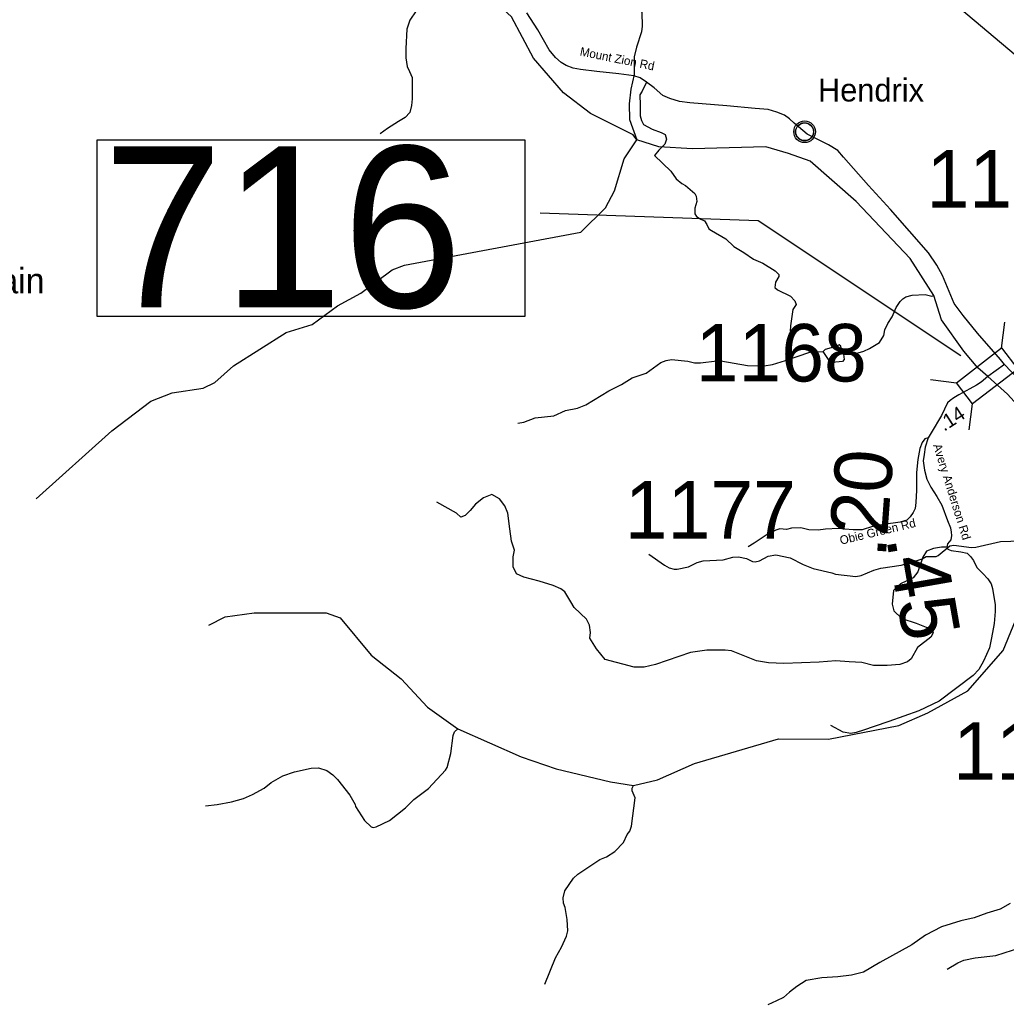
# Model space of a CAD drawing. Extents: x 1248089 to 1457196, y 820910 to 988753.
# Drawn here: x 1280420 to 1288997, y 872206 to 880738 of the extents above; entities that cross this region are included whole.
import ezdxf

# ---------------------------------------------------------------- set-up
doc = ezdxf.new("R2010")
doc.units = 0
for name, color, linetype in [('Exist Civil Demographics Community CELL', 7, 'Continuous'), ('Exist Civil Demographics Community Label', 7, 'Continuous'), ('Exist Geographical Mountain Summit Label', 7, 'Continuous'), ('Exist Hydrographic Creek Single Shore', 7, 'Continuous'), ('Exist Hydrographic Misc Water Feature', 7, 'Continuous'), ('Exist Road Non-System Type 51', 7, 'Continuous'), ('Exist Road Secondary Structure Standard Bridge CELL', 7, 'Continuous'), ('Exist Road Secondary Structure Standard Bridge Number Label', 7, 'Continuous'), ('Exist Road Secondary Type 41 Attributed', 7, 'Continuous'), ('Exist Road Secondary Type 51 Attributed', 7, 'Continuous'), ('Exist Road Secondary Type 51 Label', 7, 'Continuous'), ('Prop GRAU CAT1 Cell', 7, 'Continuous'), ('Prop Lane Lines', 7, 'Continuous')]:
    doc.layers.add(name, color=color, linetype=linetype)

msp = doc.modelspace()

# ---------------------------------------------------------------- linework, layer by layer
at = {"layer": 'Exist Civil Demographics Community CELL'}
msp.add_lwpolyline([(1287166.1, 879776.9), (1287167.1, 879782.5), (1287168.8, 879789.1), (1287171.8, 879796.3), (1287174.7, 879802), (1287178, 879807.7), (1287181.8, 879812.9), (1287185.7, 879817.2), (1287190.3, 879821.8), (1287195.9, 879826.4), (1287201.3, 879830.1), (1287206.2, 879832.9), (1287211.2, 879835.4), (1287216.7, 879837.7), (1287222.3, 879839.5), (1287226.6, 879840.7), (1287231.5, 879841.4), (1287235.6, 879842.1), (1287242, 879842.4), (1287246.4, 879842.3), (1287252.1, 879842), (1287257, 879841.3), (1287261.9, 879840.3), (1287266.9, 879838.9), (1287272.1, 879837), (1287278.7, 879834), (1287285, 879830.5), (1287290, 879827), (1287295.2, 879823), (1287298.5, 879819.8), (1287302.6, 879815.5), (1287306.5, 879810.8), (1287309.6, 879806.2), (1287312.7, 879801.2), (1287315.2, 879796), (1287317.2, 879791), (1287318.8, 879786), (1287320, 879781.4), (1287321.1, 879775.3), (1287321.8, 879770.6), (1287322, 879764.6), (1287321.8, 879758.8), (1287321.3, 879753.2), (1287320.3, 879747.7), (1287318.7, 879741.5), (1287316.8, 879735.7), (1287314.5, 879730.6), (1287311.4, 879724.6), (1287308.1, 879719.3), (1287304.6, 879714.6), (1287300.4, 879709.9), (1287295.1, 879704.9), (1287290.1, 879700.8), (1287285.1, 879697.3), (1287280.8, 879694.8), (1287273.9, 879691.6), (1287266.8, 879688.9), (1287260.9, 879687.4), (1287254.2, 879686.1), (1287249.8, 879685.6), (1287245.3, 879685.4), (1287239.7, 879685.4), (1287235.5, 879685.8), (1287229.8, 879686.5), (1287223.9, 879687.8), (1287219.3, 879689.1), (1287214.2, 879691), (1287209.6, 879693), (1287205.6, 879695.2), (1287198.8, 879699.3), (1287193.3, 879703.6), (1287188.3, 879708.1), (1287183.9, 879712.9), (1287180.7, 879716.9), (1287177.7, 879721.1), (1287173.6, 879728.2), (1287171.9, 879731.7), (1287170.2, 879735.7), (1287167.6, 879743.9), (1287166.1, 879751), (1287165.4, 879756.1), (1287165.1, 879762.4), (1287165, 879767.1), (1287165.5, 879773.6)], close=True, dxfattribs=at)
for centre, radius in [((1287243.7, 879764.5), 94.3), ((1287243.4, 879764.8), 76.7)]:
    msp.add_circle(centre, radius, dxfattribs=at)
at = {"layer": 'Exist Hydrographic Creek Single Shore'}
for points in [[(1285785.8, 879695.4), (1285753.7, 879738.6), (1285382.7, 879923.3), (1285145.7, 880102.1), (1284885.7, 880402.7), (1284694.7, 880764.4), (1284596.7, 880851.8), (1284298.6, 880923.3), (1283947.7, 880907.4), (1283419.7, 881147.8)], [(1288835.1, 877637.2), (1288749.2, 877712.6), (1288628.5, 877856), (1288432.8, 878128.9), (1288366.5, 878339.5), (1288161.8, 878662.8), (1287690.8, 879158.1), (1287290.7, 879507.6), (1287102.6, 879575.8), (1286906.6, 879634.6), (1286267.7, 879616.7), (1285975.7, 879632.4), (1285785.8, 879695.4)], [(1289907.9, 876073.7), (1289876.8, 876159.8), (1289306.8, 876706.3), (1289236.9, 876917.8), (1289312.5, 877116.4), (1289121.9, 877354.4), (1289008.6, 877483.6), (1288835.1, 877637.2)]]:
    msp.add_lwpolyline(points, dxfattribs=at)
at = {"layer": 'Exist Hydrographic Misc Water Feature'}
for points in [[(1285848.1, 881734.3), (1285875.3, 881700.9), (1285909.6, 881636.2), (1285915.8, 881556.5), (1285881.7, 881393), (1285875.8, 881312.7), (1285822.5, 881184.2), (1285813.4, 881140.8), (1285813.2, 880884), (1285819.6, 880819.8), (1285827.1, 880799.9), (1285830.4, 880683.3), (1285825, 880631.7), (1285781.7, 880498.9), (1285761.7, 880415.5), (1285761.9, 880262.9), (1285732.7, 880133.8), (1285717.6, 880006), (1285720.2, 879869.8), (1285785.8, 879695.4)], [(1280563.7, 876573.1), (1281220.7, 877163.9), (1281560.7, 877423), (1281745.7, 877494.8), (1282013.7, 877535.4), (1282114.7, 877585.8), (1282276.7, 877730.4), (1282734.7, 878019.9), (1282960.6, 878087.6), (1283181.7, 878250.6), (1283384.7, 878361.4), (1283656.7, 878562.8), (1283765.7, 878603.3), (1285298.8, 878891), (1285512.7, 879103.3), (1285591.7, 879249.5), (1285673.7, 879530.1), (1285785.8, 879695.4)], [(1287581.6, 877830.7), (1287669.6, 877830.6), (1287758.3, 877856.8), (1287808.9, 877879.5), (1287894.2, 877931.2), (1287931.8, 877994.5), (1287941, 878041.8), (1287966.4, 878097.2), (1288003.8, 878156.4), (1288039.9, 878237.7), (1288073.1, 878288.7), (1288097.7, 878312), (1288122.1, 878328), (1288178.5, 878342.4), (1288290.8, 878350), (1288350.4, 878336.5), (1288366.5, 878339.5)], [(1287581.6, 877830.7), (1287569.9, 877847.4), (1287559.1, 877899.3), (1287543.5, 877911.9), (1287515.1, 877896.1), (1287422.5, 877870.9), (1287406, 877854.8)], [(1284748.8, 877231.8), (1284801.1, 877240.6), (1284902.1, 877278), (1285062.7, 877296.2), (1285163.8, 877341.7), (1285268.3, 877361), (1285341.2, 877391.5), (1285542.4, 877512.2), (1285651.8, 877565.8), (1285745.3, 877625.5), (1285866.3, 877666.6), (1285994.6, 877757.5), (1286039.1, 877776.3), (1286087.4, 877783.6), (1286227.1, 877770.1), (1286286.8, 877756.6), (1286338.8, 877755.6), (1286479.3, 877774), (1286515.3, 877772.5), (1286746.5, 877733.4), (1286890.6, 877729.7), (1286963, 877742.3), (1287075.8, 877775.3), (1287289.7, 877848.1), (1287406, 877854.8)], [(1287581.6, 877830.7), (1287588.5, 877784.7), (1287573.9, 877766.9), (1287483.7, 877757.2), (1287463.8, 877765.8), (1287406, 877854.8)], [(1285887.7, 876092.8), (1286025.6, 875997.4), (1286064.9, 875974.4), (1286108.6, 875961.2), (1286136.7, 875960.7), (1286233.3, 875982.5), (1286310.2, 876018.7), (1286362.7, 876033.3), (1286534.9, 876043), (1286619.5, 876065), (1286667.7, 876068.2), (1286739.3, 876054.5), (1286790.8, 876028.7), (1286814.7, 876026.7), (1286850.9, 876033.4), (1286926, 876075.3), (1286994.3, 876086.3), (1287117.8, 876060.8), (1287230.3, 876001.9), (1287317.6, 875968.1), (1287480.8, 875929.6), (1287512.6, 875917.5), (1287688.2, 875898.3), (1287736.4, 875905.6), (1287845.6, 875952.7), (1287906.1, 875971.1), (1288082.8, 875997.2), (1288165.5, 876019.3), (1288266.4, 876052.5), (1288298.9, 876071.6), (1288386.9, 876071.5), (1288403.1, 876079.4), (1288505.4, 876165.1), (1288541.4, 876170.1), (1288693.1, 876150.6), (1288733.2, 876153.2), (1288946.5, 876202.2), (1289126.9, 876207.6)], [(1282062.7, 875476), (1282206.8, 875548.6), (1282457.8, 875583.1), (1283082.8, 875583.6), (1283206.7, 875538.5), (1283473.8, 875214.7), (1283735.7, 875009.1), (1283963.8, 874761.7), (1284227.4, 874575), (1284778.8, 874331.7), (1285084.8, 874227), (1285556.8, 874112.6), (1285756.3, 874080.6), (1285965.8, 874130.7), (1286286.8, 874272), (1287016.9, 874487.2), (1287450.9, 874485), (1288062.9, 874604), (1288314.9, 874713.8), (1288661.9, 874903.9), (1288970.8, 875255.5), (1289209.8, 875841.6)], [(1282035.5, 873905.8), (1282135.7, 873915.3), (1282260.4, 873938.2), (1282365.2, 873968.1), (1282442.1, 874001.9), (1282543.6, 874058.1), (1282606.8, 874108.5), (1282708.2, 874164), (1282809.2, 874201.3), (1282954.1, 874232.1), (1283018.2, 874234), (1283089.6, 874212.1), (1283140.8, 874175), (1283183.7, 874132.2), (1283290.5, 873997.2), (1283336.5, 873915.8), (1283340.1, 873900.2), (1283417.2, 873778), (1283473.9, 873721), (1283493.7, 873716.5), (1283518, 873723.4), (1283633.4, 873778.5), (1283772.1, 873887.4), (1283846, 873959.8), (1283974.4, 874054.8), (1284122.4, 874215.2), (1284135, 874238.7), (1284168.1, 874360.3), (1284187.9, 874515.9), (1284200.7, 874547.6), (1284227.4, 874575)], [(1285159.3, 873165.3), (1285234.3, 873277), (1285271, 873310), (1285464.3, 873437.4), (1285521, 873462.5), (1285594.1, 873508.6), (1285668.1, 873585.1), (1285701.8, 873655.9), (1285724.5, 873683.3), (1285737.7, 873727.3), (1285769.7, 873974.5), (1285743.2, 874035), (1285743.7, 874057.2), (1285756.3, 874080.6)], [(1284985.1, 872353.8), (1285076.8, 872583.5), (1285131.1, 872675.8), (1285173.6, 872771.1), (1285184.6, 872819.3), (1285179, 872915.3), (1285161.6, 873019.9), (1285146.6, 873059.7), (1285145.6, 873103.8), (1285159.3, 873165.3)], [(1288482.7, 872483.9), (1288576.2, 872541.1), (1288628.8, 872563.9), (1288725.3, 872584.1), (1288905.9, 872603.4), (1289123.8, 872672.1), (1289223.9, 872673.4), (1289295.5, 872658), (1289383.5, 872652.1), (1289495.8, 872661.4), (1289632.6, 872695.6), (1289657.1, 872711.5), (1289697.2, 872718.1), (1289810.6, 872771.6), (1289869.5, 872804.1), (1289898.8, 872855.3), (1289938.7, 873004.1), (1289955.4, 873023.3), (1289985.9, 873048.8)]]:
    msp.add_lwpolyline(points, dxfattribs=at)
at = {"layer": 'Exist Road Non-System Type 51'}
for points in [[(1284008.2, 881092.6), (1283967.8, 881032), (1283933, 880948), (1283900.2, 880866), (1283865.4, 880814.8), (1283812.2, 880734.8), (1283785.6, 880654.9), (1283775.3, 880488.9), (1283775.3, 880406.9), (1283787.6, 880330.3), (1283808.1, 880287.2), (1283830.6, 880236), (1283830.6, 880141.7), (1283830.6, 880049.5), (1283826.5, 879992.1), (1283810.1, 879932.7), (1283771.2, 879889.6), (1283713.9, 879854.8), (1283615.6, 879793.3), (1283552.4, 879747)], [(1285868.8, 880195), (1285830.6, 880116.1), (1285811.6, 880086.2), (1285814.3, 879996.8), (1285814.3, 879901.9), (1285825.1, 879861.2), (1285844.1, 879825.9), (1285917.3, 879788), (1285995.8, 879758.2), (1286031.1, 879739.2), (1286041.9, 879698.5), (1286028.3, 879657.8), (1285976.9, 879603.6), (1285938.9, 879557.5), (1286079.7, 879420.5), (1286125.8, 879355.5), (1286174.5, 879314.8), (1286207, 879298.5), (1286247.7, 879263.3), (1286288.3, 879228), (1286299.2, 879203.6), (1286307.3, 879157.5), (1286288.3, 879100.6), (1286288.3, 879051.8), (1286304.6, 879027.4), (1286342.5, 879003), (1286372.3, 878989.4), (1286394, 878956.9), (1286410.3, 878921.6), (1286434.6, 878905.4), (1286559.3, 878832.2), (1286627, 878767.1), (1286713.7, 878715.6), (1286797.7, 878655.9), (1286879, 878620.7), (1286987.4, 878555.6), (1287019, 878524.3), (1287019, 878505.3), (1286989.2, 878456.5), (1286983.8, 878410.4), (1287008.2, 878388.7), (1287122, 878334.5), (1287157.2, 878293.8), (1287170.8, 878264), (1287141, 878217.9), (1287138.3, 878198.9), (1287119.3, 878076.9), (1287116.6, 878030.8)], [(1288481.1, 876154), (1288434.4, 876153.3), (1288365.3, 876142.4), (1288303.6, 876117), (1288270.9, 876066.1), (1288227.3, 875938.9), (1288187.4, 875888), (1288078.4, 875833.5), (1288016.6, 875775.3), (1288005.7, 875659), (1288020.3, 875600.8), (1288089.3, 875531.7), (1288212.8, 875491.8), (1288300, 875459), (1288350.8, 875440.9), (1288361.7, 875408.2), (1288339.9, 875371.8), (1288223.7, 875280.9), (1288169.2, 875182.8), (1288136.5, 875157.3), (1288071.1, 875131.9), (1287962.2, 875124.6), (1287842.3, 875124.6), (1287740.6, 875150.1), (1287631.6, 875157.3), (1287515.4, 875164.6), (1287370.1, 875153.7), (1287061.3, 875142.8), (1286930.6, 875146.4), (1286825.2, 875164.6), (1286607.3, 875251.9), (1286552.8, 875259.1), (1286393, 875259.1), (1286251.3, 875237.3), (1285946.2, 875131.9), (1285849.5, 875110.2), (1285762.4, 875110.2), (1285508.1, 875175.6), (1285435.4, 875270.1), (1285377.3, 875361), (1285381, 875411.9), (1285373.7, 875473.7), (1285348.3, 875528.2), (1285239.3, 875630), (1285210.2, 875677.3), (1285159.4, 875764.5), (1285123.1, 875789.9), (1285057.7, 875819), (1284934.2, 875859), (1284803.4, 875891.7), (1284738, 875920.8), (1284709, 875982.6), (1284709, 876069.8), (1284719.9, 876128), (1284694.4, 876204.3), (1284680.7, 876311.9), (1284662.5, 876450.1), (1284637.1, 876511.9), (1284589.9, 876573.7), (1284524.5, 876610), (1284451.8, 876580.9), (1284382.8, 876526.4), (1284335.6, 876471.9), (1284292, 876428.3), (1284255.7, 876413.7), (1284215.7, 876450.1), (1284045, 876544.6)], [(1287834.7, 876331.7), (1287743.6, 876304.2), (1287666.9, 876304.2), (1287593.1, 876310.1), (1287537, 876316), (1287424.8, 876310.1), (1287359.8, 876301.2), (1287280.1, 876304.2), (1287209.3, 876321.9), (1287129.5, 876319), (1287085.3, 876307.1), (1287029.2, 876313.1), (1286952.4, 876286.5), (1286804.8, 876189), (1286751.6, 876156.5)], [(1288708.9, 875037.8), (1288412.8, 874814.3), (1288235.7, 874731.5), (1287975.9, 874637), (1287848.9, 874595.6), (1287754.4, 874563.1), (1287692.4, 874542.4), (1287645.2, 874533.6), (1287577.3, 874545.4), (1287471, 874601.5)], [(1289029.5, 873055.4), (1288942.6, 873007.7), (1288827.7, 872971.2), (1288718.4, 872932), (1288600.7, 872903.9), (1288432.5, 872853.4), (1288295.2, 872780.5), (1288174.6, 872696.4), (1287898.5, 872543), (1287755.6, 872458.8), (1287651.9, 872433.6), (1287531.3, 872416.8), (1287394, 872408.4), (1287256.7, 872385.9), (1287175.4, 872335.4), (1287110.9, 872284.9), (1287060.5, 872237.3), (1286998.8, 872209.2), (1286923.1, 872175.6)]]:
    msp.add_lwpolyline(points, dxfattribs=at)
at = {"layer": 'Exist Road Secondary Structure Standard Bridge CELL'}
for p, q in [((1288956.2, 877884.1), (1288985.3, 878108.6)), ((1288338.4, 877611.4), (1288562.8, 877582.4)), ((1288675.1, 877174.4), (1288704.2, 877398.9))]:
    msp.add_line(p, q, dxfattribs=at)
msp.add_lwpolyline([(1288562.8, 877582.4), (1288955.5, 877885), (1289096.9, 877701.5), (1288704.2, 877398.9)], close=True, dxfattribs=at)
at = {"layer": 'Exist Road Secondary Structure Standard Bridge Number Label'}
msp.add_line((1290947.6, 878846.4), (1286961.2, 882216.8), dxfattribs=at)
msp.add_lwpolyline([(1281093.8, 879694.1), (1284809.7, 879694.1), (1284809.7, 878157.7), (1281093.8, 878157.7)], close=True, dxfattribs=at)
msp.add_lwpolyline([(1288602.6, 877815.3), (1286838.7, 878991.2), (1284944.2, 879056.6)], dxfattribs=at)
at = {"layer": 'Exist Road Secondary Type 41 Attributed'}
for points in [[(1288982, 877742.4), (1288835.1, 877637.2)], [(1288835.1, 877637.2), (1288777.1, 877588.1), (1288739.1, 877561.8), (1288681.1, 877530.5), (1288585.4, 877476.2), (1288542.1, 877450.6), (1288508.7, 877429), (1288487.1, 877407.3), (1288432.1, 877297.2), (1288343.6, 877147.7), (1288316.3, 877105)], [(1288316.3, 877105), (1288292.7, 877022.4), (1288282.8, 876957.5), (1288275, 876902.4), (1288284.8, 876823.8), (1288306.4, 876745.1), (1288339.8, 876674.3), (1288392.7, 876594.6), (1288435.9, 876517.9), (1288487, 876386.1), (1288512.6, 876321.2), (1288518.5, 876283.9), (1288520.4, 876254.4), (1288514.5, 876217), (1288487, 876183.5), (1288481.1, 876154), (1288489, 876136.3), (1288518.5, 876124.5), (1288601, 876112.7), (1288655.5, 876102.2), (1288687, 876070.7), (1288712.5, 876037.3), (1288742, 875976.3), (1288793.1, 875925.2), (1288836.4, 875877.9), (1288863.9, 875834.7), (1288875.7, 875793.4), (1288885.5, 875738.3), (1288899.3, 875655.7), (1288901.2, 875594.7), (1288891.4, 875490.5), (1288868.1, 875365.8), (1288850.4, 875277.2), (1288797.4, 875161.2), (1288757, 875088.3), (1288708.9, 875037.8)]]:
    msp.add_lwpolyline(points, dxfattribs=at)
at = {"layer": 'Exist Road Secondary Type 51 Attributed'}
for points in [[(1288982, 877742.4), (1288945.4, 877785.6), (1288745.3, 878014.3), (1288620.8, 878167.7), (1288544.8, 878272.6), (1288441.3, 878513.8), (1288392, 878605.8), (1288319.9, 878712), (1287990.2, 879087.6), (1287799.1, 879298.3), (1287580.3, 879542.1), (1287531.9, 879601.1), (1287451.2, 879650.2), (1287356.9, 879697.4), (1287265.2, 879744.6), (1287151.2, 879840.3), (1287113.2, 879877), (1287067.4, 879907.1), (1287001.9, 879934.7), (1286925.9, 879956.9), (1286812.7, 879967.3), (1286566.5, 879988.3), (1286244.8, 880016.7), (1286155.7, 880028.5), (1286070.6, 880052.1), (1286010.3, 880078.3), (1285934.3, 880145.1), (1285868.8, 880195), (1285813.8, 880234.3), (1285757.5, 880251.3), (1285626.9, 880268.2), (1285437.3, 880287.7), (1285295.8, 880304.8), (1285231.6, 880316.6), (1285170, 880340.2), (1285128.1, 880366.4), (1285078.3, 880409.7), (1285022, 880477.8), (1284922.8, 880650), (1284828.5, 880798.1)], [(1291859.2, 875828.6), (1291574.7, 875951), (1291381.4, 876029.7), (1291219.2, 876097), (1290988.9, 876191.4), (1290851.3, 876256.9), (1290754.6, 876312.7), (1290697.3, 876347.1), (1290635, 876396.3), (1290561.3, 876460.2), (1290371.8, 876625.3), (1290085.1, 876874.5), (1289903.3, 877035.1), (1289843.4, 877086.4), (1289784.4, 877134), (1289645.2, 877214.3), (1289497.7, 877296.3), (1289424, 877338.9), (1289342.1, 877404.5), (1289217.6, 877507.8), (1289101.3, 877617.6), (1288982, 877742.4)], [(1288316.3, 877105), (1288289.8, 877094.1), (1288266.2, 877062.6), (1288244.6, 877009.5), (1288228.9, 876915.1), (1288215.1, 876801), (1288217.1, 876647.6), (1288209.2, 876541.4), (1288203.4, 876489), (1288187.7, 876455.5), (1288160.2, 876416.2), (1288130.7, 876388.6), (1288073.7, 876370.9), (1287928.3, 876351.3), (1287834.7, 876331.7)]]:
    msp.add_lwpolyline(points, dxfattribs=at)

# ---------------------------------------------------------------- texts
at = {"layer": 'Exist Civil Demographics Community Label'}
msp.add_text('Hendrix', height=200, dxfattribs=at).set_placement((1287359.6, 880027.1))
at = {"layer": 'Exist Geographical Mountain Summit Label'}
msp.add_text('Parmer Mountain', height=220, dxfattribs=at).set_placement((1278378.9, 878359.2))
at = {"layer": 'Exist Road Secondary Structure Standard Bridge Number Label'}
msp.add_text('716', height=1400, dxfattribs=at).set_placement((1281143.9, 878236.8))
at = {"layer": 'Exist Road Secondary Type 51 Label'}
for s, rotation, p in [('Mount Zion Rd', 348.43822, (1285285.1, 880428.3)), ('Avery Anderson Rd', 287.40793, (1288358.7, 877038.7)), ('Obie Green Rd', 13.42584, (1287558.9, 876174.1))]:
    msp.add_text(s, height=75, rotation=rotation, dxfattribs=at).set_placement(p)
at = {"layer": 'Prop GRAU CAT1 Cell'}
for s, height, rotation, p in [('.14', 125, 32.92612, (1288456.8, 877155.6)), ('.20', 500, 85.76691, (1287948, 876055.2)), ('.45', 500, 279.89697, (1287951.6, 876231.5))]:
    msp.add_text(s, height=height, rotation=rotation, dxfattribs=at).set_placement(p)
at = {"layer": 'Prop Lane Lines'}
for s, p in [('1155', (1288303.4, 879104.5)), ('1168', (1286296.6, 877593.3)), ('1177', (1285679.9, 876227.6)), ('1168', (1288535.7, 874131.8))]:
    msp.add_text(s, height=500, dxfattribs=at).set_placement(p)

doc.saveas('drawing.dxf')
